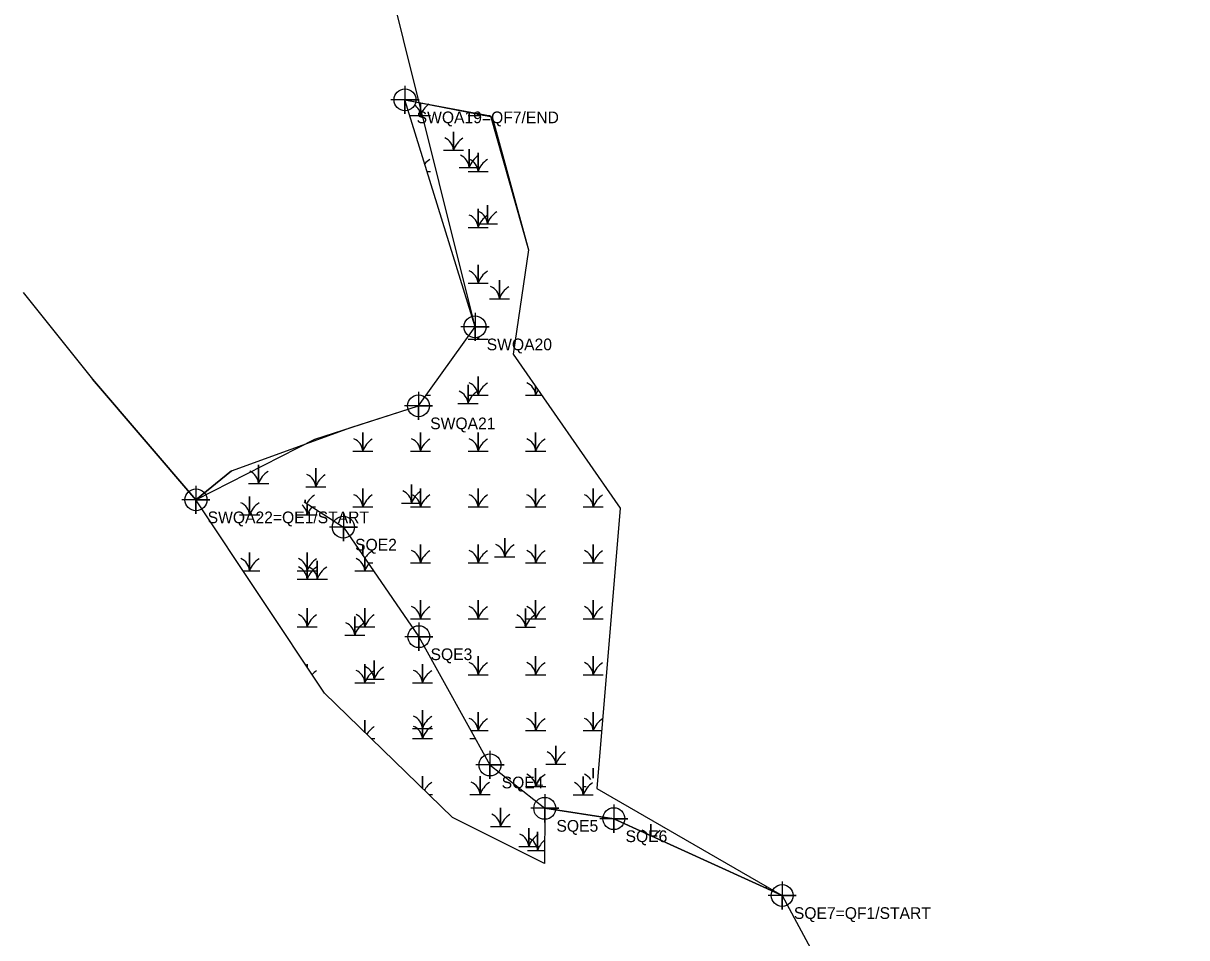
# Model space of a CAD drawing. Extents: x 1705487 to 1707934, y 819100 to 822252.
# Drawn here: x 1705522.6 to 1705771.1, y 821476.4 to 821671.8 of the extents above; entities that cross this region are included whole.
import ezdxf

# ---------------------------------------------------------------- set-up
doc = ezdxf.new("R2010")
doc.units = 0
for name, color, linetype in [('Exist Environmental Wetland Boundary', 7, 'Continuous'), ('Exist Hydro Jurisdictional Stream or Body of Water Mitigable', 7, 'Continuous'), ('Exist Hydro Jurisdictional Stream or Body of Water NEU Mitigable Cogo Comment', 7, 'Continuous'), ('Exist Hydro Jurisdictional Stream or Body of Water NEU Mitigable Cogo Point CELL', 7, 'Continuous'), ('Exist Hydro Jurisdictional Stream or Body of Water NEU NonMitigable', 7, 'Continuous'), ('Exist Hydro Jurisdictional Stream or Body of Water NonMitigable', 7, 'Continuous'), ('Exist Hydro Swamp or Marsh', 7, 'Continuous')]:
    doc.layers.add(name, color=color, linetype=linetype)

msp = doc.modelspace()

# ---------------------------------------------------------------- linework, layer by layer
at = {"layer": 'Exist Environmental Wetland Boundary'}
msp.add_lwpolyline([(1705604.14, 821655.41), (1705622.78, 821651.76), (1705630.51, 821623.38), (1705627.25, 821601.08), (1705650.12, 821568.21), (1705645.11, 821508.28), (1705684.69, 821485.45), (1705648.75, 821501.86), (1705633.99, 821504.08), (1705633.92, 821492.29), (1705614.31, 821502.09), (1705586.96, 821528.65), (1705559.5, 821569.97), (1705567.07, 821576.19), (1705592.56, 821585.44), (1705607.03, 821590.04), (1705619.1, 821606.91)], close=True, dxfattribs=at)
for points in [[(1705604.14, 821655.41), (1705622.42, 821652.01), (1705630.51, 821623.38), (1705627.25, 821601.08), (1705650.12, 821568.21), (1705645.11, 821508.28), (1705684.69, 821485.45)], [(1705633.99, 821504.08), (1705633.92, 821492.29), (1705614.31, 821502.09), (1705586.96, 821528.65), (1705559.5, 821569.97)]]:
    msp.add_lwpolyline(points, dxfattribs=at)
at = {"layer": 'Exist Hydro Jurisdictional Stream or Body of Water Mitigable'}
msp.add_lwpolyline([(1705582.59, 821569.54), (1705590.99, 821564.14), (1705607.1, 821540.73), (1705622.29, 821513.34), (1705633.99, 821504.08), (1705648.75, 821501.86), (1705684.69, 821485.45), (1705697.35, 821461.9), (1705714.35, 821444.54), (1705718.97, 821436.82), (1705733.81, 821397), (1705747.25, 821370.34), (1705757.77, 821347.12), (1705771.09, 821344.32)], dxfattribs=at)
at = {"layer": 'Exist Hydro Jurisdictional Stream or Body of Water NEU Mitigable Cogo Point CELL'}
for points in [[(1705604.14, 821658.41), (1705604.14, 821652.41), (1705604.14, 821655.41), (1705607.14, 821655.41), (1705601.14, 821655.41)], [(1705619.1, 821609.91), (1705619.1, 821603.91), (1705619.1, 821606.91), (1705622.1, 821606.91), (1705616.1, 821606.91)], [(1705607.03, 821593.04), (1705607.03, 821587.04), (1705607.03, 821590.04), (1705610.03, 821590.04), (1705604.03, 821590.04)], [(1705559.5, 821572.97), (1705559.5, 821566.97), (1705559.5, 821569.97), (1705562.5, 821569.97), (1705556.5, 821569.97)], [(1705590.99, 821567.14), (1705590.99, 821561.14), (1705590.99, 821564.14), (1705593.99, 821564.14), (1705587.99, 821564.14)], [(1705607.1, 821543.73), (1705607.1, 821537.73), (1705607.1, 821540.73), (1705610.1, 821540.73), (1705604.1, 821540.73)], [(1705622.29, 821516.34), (1705622.29, 821510.34), (1705622.29, 821513.34), (1705625.29, 821513.34), (1705619.29, 821513.34)], [(1705633.99, 821507.08), (1705633.99, 821501.08), (1705633.99, 821504.08), (1705636.99, 821504.08), (1705630.99, 821504.08)], [(1705648.75, 821504.86), (1705648.75, 821498.86), (1705648.75, 821501.86), (1705651.75, 821501.86), (1705645.75, 821501.86)], [(1705684.69, 821488.45), (1705684.69, 821482.45), (1705684.69, 821485.45), (1705687.69, 821485.45), (1705681.69, 821485.45)]]:
    msp.add_lwpolyline(points, dxfattribs=at)
for centre in [(1705604.14, 821655.41), (1705619.1, 821606.91), (1705607.03, 821590.04), (1705559.5, 821569.97), (1705590.99, 821564.14), (1705607.1, 821540.73), (1705622.29, 821513.34), (1705633.99, 821504.08), (1705648.75, 821501.86), (1705684.69, 821485.45)]:
    msp.add_circle(centre, 2.34, dxfattribs=at)
at = {"layer": 'Exist Hydro Jurisdictional Stream or Body of Water NEU NonMitigable'}
msp.add_lwpolyline([(1705567.07, 821576.19), (1705559.5, 821569.97), (1705537.43, 821595.75)], dxfattribs=at)
at = {"layer": 'Exist Hydro Jurisdictional Stream or Body of Water NonMitigable'}
msp.add_lwpolyline([(1705522.62, 821614.23), (1705537.43, 821595.75), (1705559.5, 821569.97), (1705584.92, 821582.92), (1705607.03, 821590.04), (1705619.1, 821606.91), (1705596.17, 821699.17)], dxfattribs=at)
at = {"layer": 'Exist Hydro Swamp or Marsh'}
for p, q in [((1705614.52, 821646.44), (1705614.52, 821646.44)), ((1705617.86, 821642.74), (1705617.86, 821642.74)), ((1705608.86, 821640.12), (1705609.6, 821640.12)), ((1705621.76, 821630.73), (1705621.76, 821630.73)), ((1705624.31, 821614.71), (1705624.31, 821614.71)), ((1705608.67, 821592.34), (1705609.6, 821592.34)), ((1705617.6, 821592.34), (1705617.6, 821592.34)), ((1705572.89, 821575.25), (1705572.89, 821575.25)), ((1705585.1, 821574.54), (1705585.1, 821574.54)), ((1705582.85, 821569.37), (1705582.85, 821569.95)), ((1705582.85, 821569.95), (1705582.85, 821569.37)), ((1705605.56, 821571.07), (1705605.56, 821571.07)), ((1705584.29, 821568.45), (1705585, 821568.45)), ((1705625.44, 821559.59), (1705625.44, 821559.59)), ((1705596.25, 821556.5), (1705597.3, 821556.5)), ((1705583.27, 821554.8), (1705583.27, 821554.8)), ((1705585.42, 821554.8), (1705585.42, 821554.8)), ((1705629.9, 821544.56), (1705629.9, 821544.56)), ((1705593.42, 821542.86), (1705593.42, 821542.86)), ((1705597.58, 821533.47), (1705597.58, 821533.47)), ((1705607.87, 821522.91), (1705607.87, 821522.91)), ((1705596.94, 821518.97), (1705597.72, 821518.97)), ((1705618.02, 821518.97), (1705619.17, 821518.97)), ((1705636.36, 821515.29), (1705636.36, 821515.29)), ((1705609.23, 821507.02), (1705610.02, 821507.02)), ((1705642.2, 821508.72), (1705642.81, 821508.72)), ((1705642.2, 821508.72), (1705642.2, 821508.72)), ((1705624.56, 821501.99), (1705624.56, 821501.99)), ((1705630.58, 821497.69), (1705630.58, 821497.69)), ((1705681.26, 821487.02), (1705681.26, 821487.43)), ((1705681.26, 821487.43), (1705681.26, 821487.02))]:
    msp.add_line(p, q, dxfattribs=at)
for points in [[(1705605.3, 821652.06), (1705607.45, 821652.06), (1705607.45, 821654.79)], [(1705607.45, 821654.79), (1705607.45, 821652.06), (1705609.6, 821652.06)], [(1705617.6, 821652.06), (1705619.75, 821652.06), (1705619.75, 821652.51)], [(1705619.75, 821652.51), (1705619.75, 821652.06), (1705620.07, 821652.06)], [(1705612.37, 821644.66), (1705614.52, 821644.66), (1705614.52, 821648.6), (1705614.52, 821644.66), (1705616.67, 821644.66)], [(1705615.71, 821640.95), (1705617.86, 821640.95), (1705617.86, 821644.9), (1705617.86, 821640.95), (1705620.01, 821640.95)], [(1705617.6, 821640.12), (1705619.75, 821640.12), (1705619.75, 821644.06), (1705619.75, 821640.12), (1705621.9, 821640.12)], [(1705617.6, 821628.17), (1705619.75, 821628.17), (1705619.75, 821632.12), (1705619.75, 821628.17), (1705621.9, 821628.17)], [(1705619.61, 821628.94), (1705621.76, 821628.94), (1705621.76, 821632.89), (1705621.76, 821628.94), (1705623.91, 821628.94)], [(1705617.6, 821616.23), (1705619.75, 821616.23), (1705619.75, 821620.17), (1705619.75, 821616.23), (1705621.9, 821616.23)], [(1705622.16, 821612.93), (1705624.31, 821612.93), (1705624.31, 821616.87), (1705624.31, 821612.93), (1705626.46, 821612.93)], [(1705617.6, 821604.28), (1705619.75, 821604.28), (1705619.75, 821604.66)], [(1705619.75, 821604.66), (1705619.75, 821604.28), (1705621.9, 821604.28)], [(1705617.6, 821592.34), (1705619.75, 821592.34), (1705619.75, 821596.28), (1705619.75, 821592.34), (1705621.9, 821592.34)], [(1705615.45, 821590.55), (1705617.6, 821590.55), (1705617.6, 821594.5), (1705617.6, 821590.55), (1705619.75, 821590.55)], [(1705629.9, 821592.34), (1705632.05, 821592.34), (1705632.05, 821594.18)], [(1705632.05, 821594.18), (1705632.05, 821592.34), (1705633.34, 821592.34)], [(1705593, 821580.39), (1705595.15, 821580.39), (1705595.15, 821584.34), (1705595.15, 821580.39), (1705597.3, 821580.39)], [(1705605.3, 821580.39), (1705607.45, 821580.39), (1705607.45, 821584.34), (1705607.45, 821580.39), (1705609.6, 821580.39)], [(1705617.6, 821580.39), (1705619.75, 821580.39), (1705619.75, 821584.34), (1705619.75, 821580.39), (1705621.9, 821580.39)], [(1705629.9, 821580.39), (1705632.05, 821580.39), (1705632.05, 821584.34), (1705632.05, 821580.39), (1705634.2, 821580.39)], [(1705570.74, 821573.47), (1705572.89, 821573.47), (1705572.89, 821577.41), (1705572.89, 821573.47), (1705575.04, 821573.47)], [(1705582.95, 821572.75), (1705585.1, 821572.75), (1705585.1, 821576.7), (1705585.1, 821572.75), (1705587.25, 821572.75)], [(1705593, 821568.45), (1705595.15, 821568.45), (1705595.15, 821572.39), (1705595.15, 821568.45), (1705597.3, 821568.45)], [(1705603.41, 821569.28), (1705605.56, 821569.28), (1705605.56, 821573.23), (1705605.56, 821569.28), (1705607.71, 821569.28)], [(1705605.3, 821568.45), (1705607.45, 821568.45), (1705607.45, 821572.39), (1705607.45, 821568.45), (1705609.6, 821568.45)], [(1705617.6, 821568.45), (1705619.75, 821568.45), (1705619.75, 821572.39), (1705619.75, 821568.45), (1705621.9, 821568.45)], [(1705629.9, 821568.45), (1705632.05, 821568.45), (1705632.05, 821572.39), (1705632.05, 821568.45), (1705634.2, 821568.45)], [(1705642.2, 821568.45), (1705644.35, 821568.45), (1705644.35, 821572.39), (1705644.35, 821568.45), (1705646.5, 821568.45)], [(1705568.82, 821566.75), (1705570.97, 821566.75), (1705570.97, 821570.69), (1705570.97, 821566.75), (1705573.12, 821566.75)], [(1705581.12, 821566.75), (1705583.27, 821566.75), (1705583.27, 821569.1)], [(1705583.27, 821569.1), (1705583.27, 821566.75), (1705585.42, 821566.75)], [(1705623.29, 821557.81), (1705625.44, 821557.81), (1705625.44, 821561.76), (1705625.44, 821557.81), (1705627.59, 821557.81)], [(1705569.58, 821554.8), (1705570.97, 821554.8), (1705570.97, 821558.75), (1705570.97, 821554.8), (1705573.12, 821554.8)], [(1705581.12, 821554.8), (1705583.27, 821554.8), (1705583.27, 821558.75), (1705583.27, 821554.8), (1705585.42, 821554.8)], [(1705595.15, 821558.09), (1705595.15, 821560.45), (1705595.15, 821558.09)], [(1705605.3, 821556.5), (1705607.45, 821556.5), (1705607.45, 821560.45), (1705607.45, 821556.5), (1705609.6, 821556.5)], [(1705617.6, 821556.5), (1705619.75, 821556.5), (1705619.75, 821560.45), (1705619.75, 821556.5), (1705621.9, 821556.5)], [(1705629.9, 821556.5), (1705632.05, 821556.5), (1705632.05, 821560.45), (1705632.05, 821556.5), (1705634.2, 821556.5)], [(1705642.2, 821556.5), (1705644.35, 821556.5), (1705644.35, 821560.45), (1705644.35, 821556.5), (1705646.5, 821556.5)], [(1705581.12, 821553.02), (1705583.27, 821553.02), (1705583.27, 821556.96), (1705583.27, 821553.02), (1705585.42, 821553.02)], [(1705583.27, 821553.02), (1705585.42, 821553.02), (1705585.42, 821556.96), (1705585.42, 821553.02), (1705587.57, 821553.02)], [(1705593.42, 821554.8), (1705595.57, 821554.8), (1705595.57, 821557.48)], [(1705595.57, 821557.48), (1705595.57, 821554.8), (1705597.42, 821554.8)], [(1705581.12, 821542.86), (1705583.27, 821542.86), (1705583.27, 821546.8), (1705583.27, 821542.86), (1705585.42, 821542.86)], [(1705593.42, 821542.86), (1705595.57, 821542.86), (1705595.57, 821546.8), (1705595.57, 821542.86), (1705597.72, 821542.86)], [(1705605.3, 821544.56), (1705607.45, 821544.56), (1705607.45, 821548.5), (1705607.45, 821544.56), (1705609.6, 821544.56)], [(1705617.6, 821544.56), (1705619.75, 821544.56), (1705619.75, 821548.5), (1705619.75, 821544.56), (1705621.9, 821544.56)], [(1705627.75, 821542.77), (1705629.9, 821542.77), (1705629.9, 821546.72), (1705629.9, 821542.77), (1705632.05, 821542.77)], [(1705629.9, 821544.56), (1705632.05, 821544.56), (1705632.05, 821548.5), (1705632.05, 821544.56), (1705634.2, 821544.56)], [(1705642.2, 821544.56), (1705644.35, 821544.56), (1705644.35, 821548.5), (1705644.35, 821544.56), (1705646.5, 821544.56)], [(1705591.27, 821541.07), (1705593.42, 821541.07), (1705593.42, 821545.02), (1705593.42, 821541.07), (1705595.57, 821541.07)], [(1705617.6, 821532.61), (1705619.75, 821532.61), (1705619.75, 821536.56), (1705619.75, 821532.61), (1705621.9, 821532.61)], [(1705629.9, 821532.61), (1705632.05, 821532.61), (1705632.05, 821536.56), (1705632.05, 821532.61), (1705634.2, 821532.61)], [(1705642.2, 821532.61), (1705644.35, 821532.61), (1705644.35, 821536.56), (1705644.35, 821532.61), (1705646.5, 821532.61)], [(1705583.27, 821534.2), (1705583.27, 821534.86), (1705583.27, 821534.2)], [(1705593.42, 821530.91), (1705595.57, 821530.91), (1705595.57, 821534.86), (1705595.57, 821530.91), (1705597.72, 821530.91)], [(1705595.43, 821531.68), (1705597.58, 821531.68), (1705597.58, 821535.63), (1705597.58, 821531.68), (1705599.73, 821531.68)], [(1705605.72, 821530.91), (1705607.87, 821530.91), (1705607.87, 821534.86), (1705607.87, 821530.91), (1705610.02, 821530.91)], [(1705605.72, 821521.13), (1705607.87, 821521.13), (1705607.87, 821525.07), (1705607.87, 821521.13), (1705610.02, 821521.13)], [(1705618.23, 821520.67), (1705619.75, 821520.67), (1705619.75, 821524.61), (1705619.75, 821520.67), (1705621.9, 821520.67)], [(1705629.9, 821520.67), (1705632.05, 821520.67), (1705632.05, 821524.61), (1705632.05, 821520.67), (1705634.2, 821520.67)], [(1705642.2, 821520.67), (1705644.35, 821520.67), (1705644.35, 821524.61), (1705644.35, 821520.67), (1705646.15, 821520.67)], [(1705595.57, 821520.29), (1705595.57, 821522.91), (1705595.57, 821520.29)], [(1705605.72, 821518.97), (1705607.87, 821518.97), (1705607.87, 821522.91), (1705607.87, 821518.97), (1705610.02, 821518.97)], [(1705634.22, 821513.5), (1705636.37, 821513.5), (1705636.37, 821517.45), (1705636.37, 821513.5), (1705638.52, 821513.5)], [(1705629.9, 821508.72), (1705632.05, 821508.72), (1705632.05, 821512.67), (1705632.05, 821508.72), (1705634.2, 821508.72)], [(1705644.35, 821510.5), (1705644.35, 821512.67), (1705644.35, 821510.5)], [(1705607.87, 821508.34), (1705607.87, 821510.97), (1705607.87, 821508.34)], [(1705618.02, 821507.02), (1705620.17, 821507.02), (1705620.17, 821510.97), (1705620.17, 821507.02), (1705622.32, 821507.02)], [(1705640.05, 821506.94), (1705642.2, 821506.94), (1705642.2, 821510.88), (1705642.2, 821506.94), (1705644.35, 821506.94)], [(1705622.41, 821500.21), (1705624.56, 821500.21), (1705624.56, 821504.16), (1705624.56, 821500.21), (1705626.71, 821500.21)], [(1705628.43, 821495.91), (1705630.58, 821495.91), (1705630.58, 821499.86), (1705630.58, 821495.91), (1705632.73, 821495.91)], [(1705656.65, 821498.26), (1705656.65, 821500.72), (1705656.65, 821498.26)], [(1705630.32, 821495.08), (1705632.47, 821495.08), (1705632.47, 821499.02), (1705632.47, 821495.08), (1705633.94, 821495.08)]]:
    msp.add_lwpolyline(points, dxfattribs=at)
for centre, radius, start, end in [((1705604.39, 821651.84), 3.07, 4.1403, 53.6365), ((1705612.01, 821650.55), 4.81, 125.4363, 161.6222), ((1705616.69, 821651.84), 3.07, 4.1403, 12.7237), ((1705624.31, 821650.55), 4.81, 156.3437, 161.6222), ((1705611.45, 821644.43), 3.07, 4.1403, 67.535), ((1705619.08, 821643.14), 4.81, 122.1274, 161.6222), ((1705614.79, 821640.73), 3.07, 4.1403, 67.535), ((1705622.42, 821639.44), 4.81, 122.1274, 161.6222), ((1705612.01, 821638.6), 4.81, 122.1274, 139.4749), ((1705616.69, 821639.9), 3.07, 4.1403, 67.535), ((1705624.31, 821638.6), 4.81, 122.1274, 161.6222), ((1705616.69, 821627.95), 3.07, 4.1403, 67.535), ((1705618.69, 821628.72), 3.07, 4.1403, 67.535), ((1705626.32, 821627.43), 4.81, 122.1274, 161.6222), ((1705624.31, 821626.66), 4.81, 122.1274, 161.6222), ((1705616.69, 821616.01), 3.07, 4.1403, 67.535), ((1705624.31, 821614.71), 4.81, 122.1274, 161.6222), ((1705621.25, 821612.71), 3.07, 4.1403, 67.535), ((1705628.87, 821611.41), 4.81, 122.1274, 161.6222), ((1705624.31, 821602.77), 4.81, 122.1274, 126.9156), ((1705616.69, 821604.06), 3.07, 4.1403, 11.0328), ((1705624.31, 821602.77), 4.81, 156.0515, 161.6222), ((1705616.69, 821592.12), 3.07, 4.1403, 67.535), ((1705624.31, 821590.82), 4.81, 122.1274, 161.6222), ((1705628.99, 821592.12), 3.07, 4.1403, 67.535), ((1705614.54, 821590.33), 3.07, 4.1403, 67.535), ((1705622.16, 821589.04), 4.81, 122.1274, 161.6222), ((1705636.61, 821590.82), 4.81, 147.1452, 161.6222), ((1705592.08, 821580.17), 3.07, 4.1403, 67.535), ((1705599.71, 821578.88), 4.81, 122.1274, 161.6222), ((1705604.39, 821580.17), 3.07, 4.1403, 67.535), ((1705612.01, 821578.88), 4.81, 122.1274, 161.6222), ((1705616.69, 821580.17), 3.07, 4.1403, 67.535), ((1705624.31, 821578.88), 4.81, 122.1274, 161.6222), ((1705628.99, 821580.17), 3.07, 4.1403, 67.535), ((1705636.61, 821578.88), 4.81, 122.1274, 161.6222), ((1705569.82, 821573.25), 3.07, 4.1403, 67.535), ((1705577.45, 821571.95), 4.81, 122.1274, 161.6222), ((1705582.04, 821572.53), 3.07, 4.1403, 67.535), ((1705589.66, 821571.24), 4.81, 122.1274, 161.6222), ((1705602.49, 821569.06), 3.07, 4.1403, 67.535), ((1705610.12, 821567.77), 4.81, 122.1274, 161.6222), ((1705567.9, 821566.52), 3.07, 4.1403, 67.535), ((1705575.53, 821565.23), 4.81, 122.1274, 161.6222), ((1705580.2, 821566.52), 3.07, 4.1403, 50.04), ((1705587.41, 821566.93), 4.81, 122.1274, 152.2089), ((1705592.08, 821568.23), 3.07, 4.1403, 67.535), ((1705599.71, 821566.93), 4.81, 122.1274, 161.6222), ((1705604.39, 821568.23), 3.07, 4.1403, 67.535), ((1705612.01, 821566.93), 4.81, 122.1274, 161.6222), ((1705616.69, 821568.23), 3.07, 4.1403, 67.535), ((1705624.31, 821566.93), 4.81, 122.1274, 161.6222), ((1705628.99, 821568.23), 3.07, 4.1403, 67.535), ((1705636.61, 821566.93), 4.81, 122.1274, 161.6222), ((1705641.29, 821568.23), 3.07, 4.1403, 67.535), ((1705648.91, 821566.93), 4.81, 122.1274, 161.6222), ((1705587.83, 821565.23), 4.81, 137.8185, 161.6222), ((1705599.71, 821554.99), 4.81, 122.1274, 149.0776), ((1705604.39, 821556.28), 3.07, 4.1403, 67.535), ((1705612.01, 821554.99), 4.81, 122.1274, 161.6222), ((1705616.69, 821556.28), 3.07, 4.1403, 67.535), ((1705624.31, 821554.99), 4.81, 122.1274, 161.6222), ((1705622.38, 821557.59), 3.07, 4.1403, 67.535), ((1705630, 821556.3), 4.81, 122.1274, 161.6222), ((1705628.99, 821556.28), 3.07, 4.1403, 67.535), ((1705636.61, 821554.99), 4.81, 122.1274, 161.6222), ((1705641.29, 821556.28), 3.07, 4.1403, 67.535), ((1705648.91, 821554.99), 4.81, 122.1274, 161.6222), ((1705567.9, 821554.58), 3.07, 4.1403, 67.535), ((1705575.53, 821553.29), 4.81, 122.1274, 161.6222), ((1705580.2, 821554.58), 3.07, 4.1403, 67.535), ((1705587.83, 821553.29), 4.81, 122.1274, 161.6222), ((1705592.51, 821554.58), 3.07, 4.1403, 67.535), ((1705600.13, 821553.29), 4.81, 141.2112, 161.6222), ((1705580.21, 821552.8), 3.07, 4.1403, 67.535), ((1705587.83, 821551.5), 4.81, 122.1274, 161.6222), ((1705582.36, 821552.8), 3.07, 4.1403, 67.535), ((1705589.98, 821551.5), 4.81, 122.1274, 161.6222), ((1705604.39, 821544.33), 3.07, 4.1403, 67.535), ((1705612.01, 821543.04), 4.81, 122.1274, 161.6222), ((1705616.69, 821544.33), 3.07, 4.1403, 67.535), ((1705624.31, 821543.04), 4.81, 122.1274, 161.6222), ((1705628.99, 821544.33), 3.07, 4.1403, 67.535), ((1705636.61, 821543.04), 4.81, 122.1274, 161.6222), ((1705641.29, 821544.33), 3.07, 4.1403, 67.535), ((1705648.91, 821543.04), 4.81, 122.1274, 161.6222), ((1705580.2, 821542.63), 3.07, 4.1403, 67.535), ((1705587.83, 821541.34), 4.81, 122.1274, 161.6222), ((1705592.51, 821542.63), 3.07, 4.1403, 67.535), ((1705600.13, 821541.34), 4.81, 122.1274, 161.6222), ((1705626.84, 821542.55), 3.07, 4.1403, 67.535), ((1705634.46, 821541.26), 4.81, 122.1274, 161.6222), ((1705590.36, 821540.85), 3.07, 4.1403, 67.535), ((1705597.98, 821539.56), 4.81, 122.1274, 161.6222), ((1705594.51, 821531.46), 3.07, 4.1403, 67.535), ((1705602.14, 821530.17), 4.81, 122.1274, 161.6222), ((1705616.69, 821532.39), 3.07, 4.1403, 67.535), ((1705624.31, 821531.1), 4.81, 122.1274, 161.6222), ((1705628.99, 821532.39), 3.07, 4.1403, 67.535), ((1705636.61, 821531.1), 4.81, 122.1274, 161.6222), ((1705641.29, 821532.39), 3.07, 4.1403, 67.535), ((1705648.91, 821531.1), 4.81, 122.1274, 161.6222), ((1705587.83, 821529.4), 4.81, 122.1274, 137.2907), ((1705592.51, 821530.69), 3.07, 4.1403, 67.535), ((1705600.13, 821529.4), 4.81, 122.1274, 161.6222), ((1705604.81, 821530.69), 3.07, 4.1403, 67.535), ((1705612.43, 821529.4), 4.81, 122.1274, 161.6222), ((1705600.13, 821517.45), 4.81, 122.1274, 149.5699), ((1705604.81, 821520.91), 3.07, 4.1403, 67.535), ((1705604.81, 821518.74), 3.07, 4.1403, 67.535), ((1705612.43, 821519.61), 4.81, 122.1274, 161.6222), ((1705612.43, 821517.45), 4.81, 122.1274, 161.6222), ((1705616.69, 821520.44), 3.07, 4.1403, 67.535), ((1705624.31, 821519.15), 4.81, 122.1274, 161.6222), ((1705628.99, 821520.44), 3.07, 4.1403, 67.535), ((1705636.61, 821519.15), 4.81, 122.1274, 161.6222), ((1705641.29, 821520.44), 3.07, 4.1403, 67.535), ((1705648.91, 821519.15), 4.81, 122.1274, 161.6222), ((1705633.3, 821513.28), 3.07, 4.1403, 67.535), ((1705640.93, 821511.99), 4.81, 122.1274, 161.6222), ((1705612.43, 821505.51), 4.81, 122.1274, 149.5845), ((1705617.11, 821506.8), 3.07, 4.1403, 67.535), ((1705624.73, 821505.51), 4.81, 122.1274, 161.6222), ((1705628.99, 821508.5), 3.07, 4.1403, 67.535), ((1705636.61, 821507.21), 4.81, 122.1274, 161.6222), ((1705639.14, 821506.72), 3.07, 4.1403, 67.535), ((1705646.76, 821505.42), 4.81, 122.1274, 161.6222), ((1705641.29, 821508.5), 3.07, 34.4197, 67.535), ((1705621.49, 821499.99), 3.07, 4.1403, 67.535), ((1705629.12, 821498.7), 4.81, 122.1274, 161.6222), ((1705653.59, 821496.55), 3.07, 42.0749, 67.535), ((1705661.22, 821495.26), 4.81, 122.1274, 145.5096), ((1705627.52, 821495.69), 3.07, 4.1403, 67.535), ((1705635.14, 821494.4), 4.81, 122.1274, 161.6222), ((1705629.41, 821494.85), 3.07, 4.1403, 67.535), ((1705637.04, 821493.56), 4.81, 129.9178, 161.6222), ((1705685.82, 821483.32), 4.81, 134.4929, 137.5884)]:
    msp.add_arc(centre, radius, start, end, dxfattribs=at)

# ---------------------------------------------------------------- texts
at = {"layer": 'Exist Hydro Jurisdictional Stream or Body of Water NEU Mitigable Cogo Comment'}
for s, p in [('SWQA19=QF7/END', (1705606.64, 821650.41)), ('SWQA20', (1705621.6, 821601.91)), ('SWQA21', (1705609.53, 821585.04)), ('SWQA22=QE1/START', (1705562, 821564.97)), ('SQE2', (1705593.49, 821559.14)), ('SQE3', (1705609.6, 821535.73)), ('SQE4', (1705624.79, 821508.34)), ('SQE5', (1705636.49, 821499.08)), ('SQE6', (1705651.25, 821496.86)), ('SQE7=QF1/START', (1705687.19, 821480.45))]:
    msp.add_text(s, height=2.5, dxfattribs=at).set_placement(p)

doc.saveas('drawing.dxf')
